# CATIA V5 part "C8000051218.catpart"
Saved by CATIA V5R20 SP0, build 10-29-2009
Part number: C8000051218
Source: Unknown
Property "A": "30"
Property "ARTICLENO": "C8000051218"
Property "B": "13"
Property "BOMINFO": "C8000051218"
Property "C": "46"
Property "CA": "C8000051218"
Property "D1": "38"
Property "DES": "ROTATING EYEBOLT WITH RING Ton 0,5 M12x18"
Property "E": "50"
Property "H": "105"
Property "L": "18"
Property "LINA": "C8000051218"
Property "NB": "C8000051218"
Property "NBSYN": "$CODE."
Property "NN": "C800"
Property "NT": "Rotating eyebolt with ring"
Property "SIZE": "M12"
Property "SUPPLIER": "CF"
Property "SW": "30"
Property "WEIGHT": "500"
Property "WLL": "0.50"
Bounding box of the stored display mesh (mm): x -27.837 to 28, y -18 to 117.837, z -19 to 19
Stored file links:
  C:\Users\Utente\Desktop\3D files 800\C8000051218.catpart
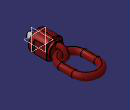
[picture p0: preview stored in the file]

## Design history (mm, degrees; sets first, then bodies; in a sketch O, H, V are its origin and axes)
Body1 "Geometry.1" (main body)
  Solid1 "C8000051218.catpart": solid without history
